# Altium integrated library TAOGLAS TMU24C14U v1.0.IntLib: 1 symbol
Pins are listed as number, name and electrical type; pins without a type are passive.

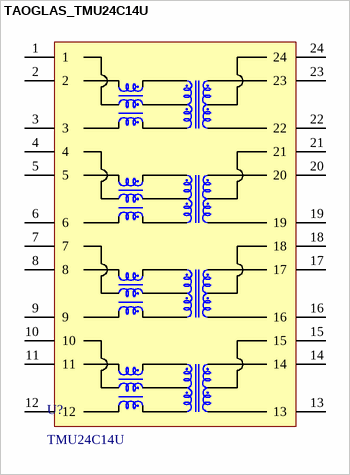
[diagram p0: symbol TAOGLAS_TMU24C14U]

## TAOGLAS_TMU24C14U
designator U?, comment TMU24C14U
1G Base-T transformer Single Port and 24pin SMT; ComponentLibStatus: Created; MFG: Taoglas; Temp_High: +85C; Temp_Low: -40C
footprint TAOGLAS_TMU24C14U (1G Base-T transformer Single Port and 24pin SMT)
pins: 1, 2, 3, 4, 5, 6, 7, 8, 9, 10, 11, 12, 13, 14, 15, 16, 17, 18, 19, 20, 21, 22, 23, 24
